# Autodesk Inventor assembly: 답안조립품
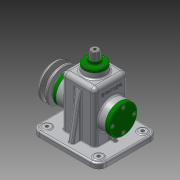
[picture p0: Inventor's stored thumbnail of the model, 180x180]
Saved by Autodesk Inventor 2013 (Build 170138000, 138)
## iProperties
Created: 2016-01
Part Number: 답안조립품
Document SubType Name: Assembly
Designer: User
Author: User
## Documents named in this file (19)
- C:\Users\User\Desktop\460126V1014\답안조립품.iam
- C:\Users\User\Desktop\460126V1014\본체.ipt
- C:\Users\User\Desktop\460126V1014\공용부품\뒤커버.ipt
- C:\Users\User\Desktop\460126V1014\공용부품\앞커버.ipt
- C:\Users\User\Desktop\460126V1014\공용부품\상부부시.ipt
- C:\Users\User\Desktop\460126V1014\공용부품\베어링 15 x 35 x 11.ipt
- C:\Users\User\Desktop\460126V1014\공용부품\오일실 15 25 7.ipt
- C:\Users\User\Desktop\460126V1014\공용부품\편심축.ipt
- C:\Users\User\Desktop\460126V1014\공용부품\키 5 x 5 x 14.ipt
- C:\Users\User\Desktop\460126V1014\공용부품\멈춤링 15 x 1.ipt
- C:\Users\User\Desktop\460126V1014\공용부품\V-벨트풀리.ipt
- C:\Users\User\Desktop\460126V1014\공용부품\볼트 M6 x 12.ipt
- C:\Users\User\Desktop\460126V1014\공용부품\와셔.ipt
- C:\Users\User\Desktop\460126V1014\공용부품\링크.ipt
- C:\Users\User\Desktop\460126V1014\공용부품\멈춤링 6 x 5.ipt
- C:\Users\User\Desktop\460126V1014\공용부품\고정핀.ipt
- C:\Users\User\Desktop\460126V1014\공용부품\슬라이드바.ipt
- C:\Users\User\Desktop\460126V1014\공용부품\볼트 M3 x 8.ipt
- C:\Users\User\Desktop\460126V1014\공용부품\볼트 M4 x 10.ipt
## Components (15 placed, 5 different names)
1. V-벨트풀리:1
2. ISO 4018 M6 x 12:1
3. 고정핀:1
4. ISO 4762 M3 x 8:1
5. ISO 4762 M3 x 8:2
6. ISO 4762 M3 x 8:3
7. ISO 4762 M3 x 8:4
8. ISO 4762 M4 x 10:1
9. ISO 4762 M4 x 10:2
10. ISO 4762 M4 x 10:3
11. ISO 4762 M4 x 10:4
12. ISO 4762 M4 x 10:5
13. ISO 4762 M4 x 10:6
14. ISO 4762 M4 x 10:7
15. ISO 4762 M4 x 10:8
